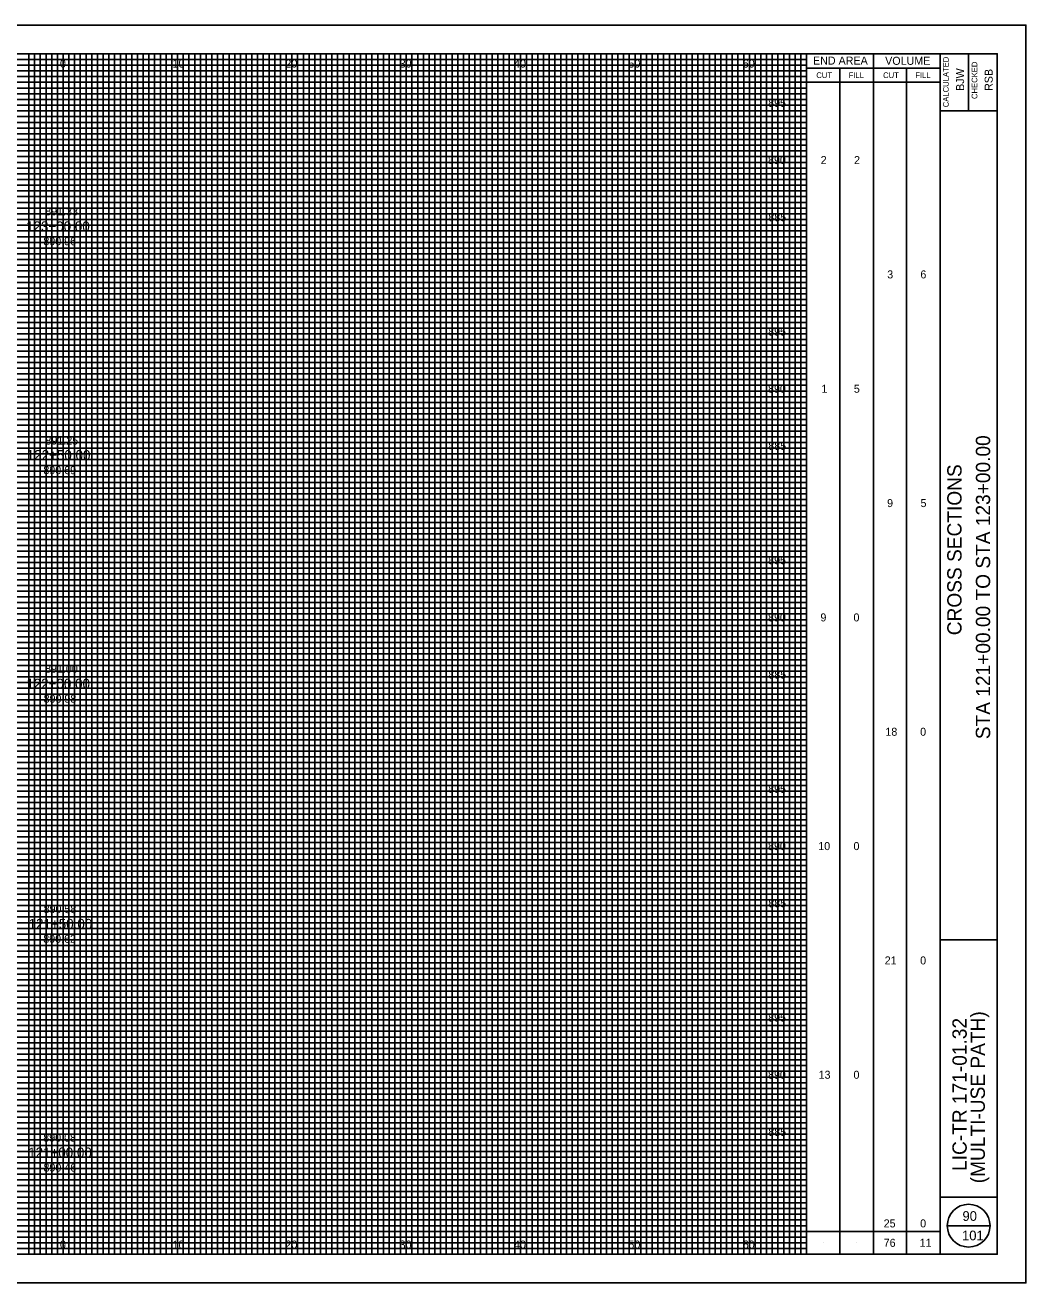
# Model space of a CAD drawing. Extents: x -10 to 160, y -2 to 3672.
# Drawn here: x 72.5 to 160, y 2412.5 to 2522.5 of the extents above; entities that cross this region are included whole.
import ezdxf

# ---------------------------------------------------------------- set-up
doc = ezdxf.new("R2010")
doc.units = 0
for name, color, linetype in [('SH_Border', 7, 'Continuous'), ('SH_Cut_Line', 7, 'Continuous'), ('SH_Data', 7, 'Continuous'), ('SH_Major_Grid_Line', 7, 'Continuous'), ('SH_Minor_Grid_Line', 7, 'Continuous'), ('SH_Text', 7, 'Continuous'), ('TX_P_10', 7, 'Continuous'), ('TX_X_10', 7, 'Continuous')]:
    doc.layers.add(name, color=color, linetype=linetype)

msp = doc.modelspace()

# ---------------------------------------------------------------- linework, layer by layer
at = {"layer": 'SH_Border'}
for p, q in [((152.5, 2415), (152.5, 2520)), ((155, 2520), (155, 2515)), ((152.5, 2515), (157.5, 2515)), ((152.5, 2442.5), (157.5, 2442.5)), ((152.5, 2420), (157.5, 2420))]:
    msp.add_line(p, q, dxfattribs=at)
msp.add_lwpolyline([(0, 2520), (157.5, 2520), (157.5, 2415), (0, 2415)], close=True, dxfattribs=at)
at = {"layer": 'SH_Cut_Line'}
msp.add_lwpolyline([(-10, 2412.5), (160, 2412.5), (160, 2522.5), (-10, 2522.5)], close=True, dxfattribs=at)
at = {"layer": 'SH_Data'}
for p, q in [((140.83, 2415), (140.83, 2520)), ((146.67, 2415), (146.67, 2520)), ((140.83, 2518.75), (152.5, 2518.75)), ((143.75, 2415), (143.75, 2518.75)), ((149.58, 2415), (149.58, 2518.75)), ((140.83, 2517.5), (152.5, 2517.5)), ((140.83, 2417), (152.5, 2417)), ((153.12, 2417.5), (156.88, 2417.5)), ((142.29, 2416), (142.29, 2416)), ((145.21, 2416), (145.21, 2416)), ((148.12, 2416), (148.12, 2416)), ((151.04, 2416), (151.04, 2416))]:
    msp.add_line(p, q, dxfattribs=at)
msp.add_circle((155, 2417.5), 1.87, dxfattribs=at)
at = {"layer": 'SH_Major_Grid_Line'}
for p, q in [((75.83, 2415), (75.83, 2520)), ((80.83, 2415), (80.83, 2520)), ((85.83, 2415), (85.83, 2520)), ((90.83, 2415), (90.83, 2520)), ((95.83, 2415), (95.83, 2520)), ((100.83, 2415), (100.83, 2520)), ((105.83, 2415), (105.83, 2520)), ((110.83, 2415), (110.83, 2520)), ((115.83, 2415), (115.83, 2520)), ((120.83, 2415), (120.83, 2520)), ((125.83, 2415), (125.83, 2520)), ((130.83, 2415), (130.83, 2520)), ((135.83, 2415), (135.83, 2520)), ((5.83, 2515), (140.83, 2515)), ((5.83, 2510), (140.83, 2510)), ((5.83, 2505), (140.83, 2505)), ((5.83, 2500), (140.83, 2500)), ((5.83, 2495), (140.83, 2495)), ((5.83, 2490), (140.83, 2490)), ((5.83, 2485), (140.83, 2485)), ((5.83, 2480), (140.83, 2480)), ((5.83, 2475), (140.83, 2475)), ((5.83, 2470), (140.83, 2470)), ((5.83, 2465), (140.83, 2465)), ((5.83, 2460), (140.83, 2460)), ((5.83, 2455), (140.83, 2455)), ((5.83, 2450), (140.83, 2450)), ((5.83, 2445), (140.83, 2445)), ((5.83, 2440), (140.83, 2440)), ((5.83, 2435), (140.83, 2435)), ((5.83, 2430), (140.83, 2430)), ((5.83, 2425), (140.83, 2425)), ((5.83, 2420), (140.83, 2420))]:
    msp.add_line(p, q, dxfattribs=at)
at = {"layer": 'SH_Minor_Grid_Line'}
for p, q in [((5.83, 2519.5), (140.83, 2519.5)), ((5.83, 2519), (140.83, 2519)), ((72.83, 2415), (72.83, 2520)), ((73.33, 2415), (73.33, 2520)), ((73.83, 2415), (73.83, 2520)), ((74.33, 2415), (74.33, 2520)), ((74.83, 2415), (74.83, 2520)), ((75.33, 2415), (75.33, 2520)), ((76.33, 2415), (76.33, 2520)), ((76.83, 2415), (76.83, 2520)), ((77.33, 2415), (77.33, 2520)), ((77.83, 2415), (77.83, 2520)), ((78.33, 2415), (78.33, 2520)), ((78.83, 2415), (78.83, 2520)), ((79.33, 2415), (79.33, 2520)), ((79.83, 2415), (79.83, 2520)), ((80.33, 2415), (80.33, 2520)), ((81.33, 2415), (81.33, 2520)), ((81.83, 2415), (81.83, 2520)), ((82.33, 2415), (82.33, 2520)), ((82.83, 2415), (82.83, 2520)), ((83.33, 2415), (83.33, 2520)), ((83.83, 2415), (83.83, 2520)), ((84.33, 2415), (84.33, 2520)), ((84.83, 2415), (84.83, 2520)), ((85.33, 2415), (85.33, 2520)), ((86.33, 2415), (86.33, 2520)), ((86.83, 2415), (86.83, 2520)), ((87.33, 2415), (87.33, 2520)), ((87.83, 2415), (87.83, 2520)), ((88.33, 2415), (88.33, 2520)), ((88.83, 2415), (88.83, 2520)), ((89.33, 2415), (89.33, 2520)), ((89.83, 2415), (89.83, 2520)), ((90.33, 2415), (90.33, 2520)), ((91.33, 2415), (91.33, 2520)), ((91.83, 2415), (91.83, 2520)), ((92.33, 2415), (92.33, 2520)), ((92.83, 2415), (92.83, 2520)), ((93.33, 2415), (93.33, 2520)), ((93.83, 2415), (93.83, 2520)), ((94.33, 2415), (94.33, 2520)), ((94.83, 2415), (94.83, 2520)), ((95.33, 2415), (95.33, 2520)), ((96.33, 2415), (96.33, 2520)), ((96.83, 2415), (96.83, 2520)), ((97.33, 2415), (97.33, 2520)), ((97.83, 2415), (97.83, 2520)), ((98.33, 2415), (98.33, 2520)), ((98.83, 2415), (98.83, 2520)), ((99.33, 2415), (99.33, 2520)), ((99.83, 2415), (99.83, 2520)), ((100.33, 2415), (100.33, 2520)), ((101.33, 2415), (101.33, 2520)), ((101.83, 2415), (101.83, 2520)), ((102.33, 2415), (102.33, 2520)), ((102.83, 2415), (102.83, 2520)), ((103.33, 2415), (103.33, 2520)), ((103.83, 2415), (103.83, 2520)), ((104.33, 2415), (104.33, 2520)), ((104.83, 2415), (104.83, 2520)), ((105.33, 2415), (105.33, 2520)), ((106.33, 2415), (106.33, 2520)), ((106.83, 2415), (106.83, 2520)), ((107.33, 2415), (107.33, 2520)), ((107.83, 2415), (107.83, 2520)), ((108.33, 2415), (108.33, 2520)), ((108.83, 2415), (108.83, 2520)), ((109.33, 2415), (109.33, 2520)), ((109.83, 2415), (109.83, 2520)), ((110.33, 2415), (110.33, 2520)), ((111.33, 2415), (111.33, 2520)), ((111.83, 2415), (111.83, 2520)), ((112.33, 2415), (112.33, 2520)), ((112.83, 2415), (112.83, 2520)), ((113.33, 2415), (113.33, 2520)), ((113.83, 2415), (113.83, 2520)), ((114.33, 2415), (114.33, 2520)), ((114.83, 2415), (114.83, 2520)), ((115.33, 2415), (115.33, 2520)), ((116.33, 2415), (116.33, 2520)), ((116.83, 2415), (116.83, 2520)), ((117.33, 2415), (117.33, 2520)), ((117.83, 2415), (117.83, 2520)), ((118.33, 2415), (118.33, 2520)), ((118.83, 2415), (118.83, 2520)), ((119.33, 2415), (119.33, 2520)), ((119.83, 2415), (119.83, 2520)), ((120.33, 2415), (120.33, 2520)), ((121.33, 2415), (121.33, 2520)), ((121.83, 2415), (121.83, 2520)), ((122.33, 2415), (122.33, 2520)), ((122.83, 2415), (122.83, 2520)), ((123.33, 2415), (123.33, 2520)), ((123.83, 2415), (123.83, 2520)), ((124.33, 2415), (124.33, 2520)), ((124.83, 2415), (124.83, 2520)), ((125.33, 2415), (125.33, 2520)), ((126.33, 2415), (126.33, 2520)), ((126.83, 2415), (126.83, 2520)), ((127.33, 2415), (127.33, 2520)), ((127.83, 2415), (127.83, 2520)), ((128.33, 2415), (128.33, 2520)), ((128.83, 2415), (128.83, 2520)), ((129.33, 2415), (129.33, 2520)), ((129.83, 2415), (129.83, 2520)), ((130.33, 2415), (130.33, 2520)), ((131.33, 2415), (131.33, 2520)), ((131.83, 2415), (131.83, 2520)), ((132.33, 2415), (132.33, 2520)), ((132.83, 2415), (132.83, 2520)), ((133.33, 2415), (133.33, 2520)), ((133.83, 2415), (133.83, 2520)), ((134.33, 2415), (134.33, 2520)), ((134.83, 2415), (134.83, 2520)), ((135.33, 2415), (135.33, 2520)), ((136.33, 2415), (136.33, 2520)), ((136.83, 2415), (136.83, 2520)), ((137.33, 2415), (137.33, 2520)), ((137.83, 2415), (137.83, 2520)), ((138.33, 2415), (138.33, 2520)), ((138.83, 2415), (138.83, 2520)), ((139.33, 2415), (139.33, 2520)), ((139.83, 2415), (139.83, 2520)), ((140.33, 2415), (140.33, 2520)), ((5.83, 2518.5), (140.83, 2518.5)), ((5.83, 2518), (140.83, 2518)), ((5.83, 2517.5), (140.83, 2517.5)), ((5.83, 2517), (140.83, 2517)), ((5.83, 2516.5), (140.83, 2516.5)), ((5.83, 2516), (140.83, 2516)), ((5.83, 2515.5), (140.83, 2515.5)), ((5.83, 2514.5), (140.83, 2514.5)), ((5.83, 2514), (140.83, 2514)), ((5.83, 2513.5), (140.83, 2513.5)), ((5.83, 2513), (140.83, 2513)), ((5.83, 2512.5), (140.83, 2512.5)), ((5.83, 2512), (140.83, 2512)), ((5.83, 2511.5), (140.83, 2511.5)), ((5.83, 2511), (140.83, 2511)), ((5.83, 2510.5), (140.83, 2510.5)), ((5.83, 2509.5), (140.83, 2509.5)), ((5.83, 2509), (140.83, 2509)), ((5.83, 2508.5), (140.83, 2508.5)), ((5.83, 2508), (140.83, 2508)), ((5.83, 2507.5), (140.83, 2507.5)), ((5.83, 2507), (140.83, 2507)), ((5.83, 2506.5), (140.83, 2506.5)), ((5.83, 2506), (140.83, 2506)), ((5.83, 2505.5), (140.83, 2505.5)), ((5.83, 2504.5), (140.83, 2504.5)), ((5.83, 2504), (140.83, 2504)), ((5.83, 2503.5), (140.83, 2503.5)), ((5.83, 2503), (140.83, 2503)), ((5.83, 2502.5), (140.83, 2502.5)), ((5.83, 2502), (140.83, 2502)), ((5.83, 2501.5), (140.83, 2501.5)), ((5.83, 2501), (140.83, 2501)), ((5.83, 2500.5), (140.83, 2500.5)), ((5.83, 2499.5), (140.83, 2499.5)), ((5.83, 2499), (140.83, 2499)), ((5.83, 2498.5), (140.83, 2498.5)), ((5.83, 2498), (140.83, 2498)), ((5.83, 2497.5), (140.83, 2497.5)), ((5.83, 2497), (140.83, 2497)), ((5.83, 2496.5), (140.83, 2496.5)), ((5.83, 2496), (140.83, 2496)), ((5.83, 2495.5), (140.83, 2495.5)), ((5.83, 2494.5), (140.83, 2494.5)), ((5.83, 2494), (140.83, 2494)), ((5.83, 2493.5), (140.83, 2493.5)), ((5.83, 2493), (140.83, 2493)), ((5.83, 2492.5), (140.83, 2492.5)), ((5.83, 2492), (140.83, 2492)), ((5.83, 2491.5), (140.83, 2491.5)), ((5.83, 2491), (140.83, 2491)), ((5.83, 2490.5), (140.83, 2490.5)), ((5.83, 2489.5), (140.83, 2489.5)), ((5.83, 2489), (140.83, 2489)), ((5.83, 2488.5), (140.83, 2488.5)), ((5.83, 2488), (140.83, 2488)), ((5.83, 2487.5), (140.83, 2487.5)), ((5.83, 2487), (140.83, 2487)), ((5.83, 2486.5), (140.83, 2486.5)), ((5.83, 2486), (140.83, 2486)), ((5.83, 2485.5), (140.83, 2485.5)), ((5.83, 2484.5), (140.83, 2484.5)), ((5.83, 2484), (140.83, 2484)), ((5.83, 2483.5), (140.83, 2483.5)), ((5.83, 2483), (140.83, 2483)), ((5.83, 2482.5), (140.83, 2482.5)), ((5.83, 2482), (140.83, 2482)), ((5.83, 2481.5), (140.83, 2481.5)), ((5.83, 2481), (140.83, 2481)), ((5.83, 2480.5), (140.83, 2480.5)), ((5.83, 2479.5), (140.83, 2479.5)), ((5.83, 2479), (140.83, 2479)), ((5.83, 2478.5), (140.83, 2478.5)), ((5.83, 2478), (140.83, 2478)), ((5.83, 2477.5), (140.83, 2477.5)), ((5.83, 2477), (140.83, 2477)), ((5.83, 2476.5), (140.83, 2476.5)), ((5.83, 2476), (140.83, 2476)), ((5.83, 2475.5), (140.83, 2475.5)), ((5.83, 2474.5), (140.83, 2474.5)), ((5.83, 2474), (140.83, 2474)), ((5.83, 2473.5), (140.83, 2473.5)), ((5.83, 2473), (140.83, 2473)), ((5.83, 2472.5), (140.83, 2472.5)), ((5.83, 2472), (140.83, 2472)), ((5.83, 2471.5), (140.83, 2471.5)), ((5.83, 2471), (140.83, 2471)), ((5.83, 2470.5), (140.83, 2470.5)), ((5.83, 2469.5), (140.83, 2469.5)), ((5.83, 2469), (140.83, 2469)), ((5.83, 2468.5), (140.83, 2468.5)), ((5.83, 2468), (140.83, 2468)), ((5.83, 2467.5), (140.83, 2467.5)), ((5.83, 2467), (140.83, 2467)), ((5.83, 2466.5), (140.83, 2466.5)), ((5.83, 2466), (140.83, 2466)), ((5.83, 2465.5), (140.83, 2465.5)), ((5.83, 2464.5), (140.83, 2464.5)), ((5.83, 2464), (140.83, 2464)), ((5.83, 2463.5), (140.83, 2463.5)), ((5.83, 2463), (140.83, 2463)), ((5.83, 2462.5), (140.83, 2462.5)), ((5.83, 2462), (140.83, 2462)), ((5.83, 2461.5), (140.83, 2461.5)), ((5.83, 2461), (140.83, 2461)), ((5.83, 2460.5), (140.83, 2460.5)), ((5.83, 2459.5), (140.83, 2459.5)), ((5.83, 2459), (140.83, 2459)), ((5.83, 2458.5), (140.83, 2458.5)), ((5.83, 2458), (140.83, 2458)), ((5.83, 2457.5), (140.83, 2457.5)), ((5.83, 2457), (140.83, 2457)), ((5.83, 2456.5), (140.83, 2456.5)), ((5.83, 2456), (140.83, 2456)), ((5.83, 2455.5), (140.83, 2455.5)), ((5.83, 2454.5), (140.83, 2454.5)), ((5.83, 2454), (140.83, 2454)), ((5.83, 2453.5), (140.83, 2453.5)), ((5.83, 2453), (140.83, 2453)), ((5.83, 2452.5), (140.83, 2452.5)), ((5.83, 2452), (140.83, 2452)), ((5.83, 2451.5), (140.83, 2451.5)), ((5.83, 2451), (140.83, 2451)), ((5.83, 2450.5), (140.83, 2450.5)), ((5.83, 2449.5), (140.83, 2449.5)), ((5.83, 2449), (140.83, 2449)), ((5.83, 2448.5), (140.83, 2448.5)), ((5.83, 2448), (140.83, 2448)), ((5.83, 2447.5), (140.83, 2447.5)), ((5.83, 2447), (140.83, 2447)), ((5.83, 2446.5), (140.83, 2446.5)), ((5.83, 2446), (140.83, 2446)), ((5.83, 2445.5), (140.83, 2445.5)), ((5.83, 2444.5), (140.83, 2444.5)), ((5.83, 2444), (140.83, 2444)), ((5.83, 2443.5), (140.83, 2443.5)), ((5.83, 2443), (140.83, 2443)), ((5.83, 2442.5), (140.83, 2442.5)), ((5.83, 2442), (140.83, 2442)), ((5.83, 2441.5), (140.83, 2441.5)), ((5.83, 2441), (140.83, 2441)), ((5.83, 2440.5), (140.83, 2440.5)), ((5.83, 2439.5), (140.83, 2439.5)), ((5.83, 2439), (140.83, 2439)), ((5.83, 2438.5), (140.83, 2438.5)), ((5.83, 2438), (140.83, 2438)), ((5.83, 2437.5), (140.83, 2437.5)), ((5.83, 2437), (140.83, 2437)), ((5.83, 2436.5), (140.83, 2436.5)), ((5.83, 2436), (140.83, 2436)), ((5.83, 2435.5), (140.83, 2435.5)), ((5.83, 2434.5), (140.83, 2434.5)), ((5.83, 2434), (140.83, 2434)), ((5.83, 2433.5), (140.83, 2433.5)), ((5.83, 2433), (140.83, 2433)), ((5.83, 2432.5), (140.83, 2432.5)), ((5.83, 2432), (140.83, 2432)), ((5.83, 2431.5), (140.83, 2431.5)), ((5.83, 2431), (140.83, 2431)), ((5.83, 2430.5), (140.83, 2430.5)), ((5.83, 2429.5), (140.83, 2429.5)), ((5.83, 2429), (140.83, 2429)), ((5.83, 2428.5), (140.83, 2428.5)), ((5.83, 2428), (140.83, 2428)), ((5.83, 2427.5), (140.83, 2427.5)), ((5.83, 2427), (140.83, 2427)), ((5.83, 2426.5), (140.83, 2426.5)), ((5.83, 2426), (140.83, 2426)), ((5.83, 2425.5), (140.83, 2425.5)), ((5.83, 2424.5), (140.83, 2424.5)), ((5.83, 2424), (140.83, 2424)), ((5.83, 2423.5), (140.83, 2423.5)), ((5.83, 2423), (140.83, 2423)), ((5.83, 2422.5), (140.83, 2422.5)), ((5.83, 2422), (140.83, 2422)), ((5.83, 2421.5), (140.83, 2421.5)), ((5.83, 2421), (140.83, 2421)), ((5.83, 2420.5), (140.83, 2420.5)), ((5.83, 2419.5), (140.83, 2419.5)), ((5.83, 2419), (140.83, 2419)), ((5.83, 2418.5), (140.83, 2418.5)), ((5.83, 2418), (140.83, 2418)), ((5.83, 2417.5), (140.83, 2417.5)), ((5.83, 2417), (140.83, 2417)), ((5.83, 2416.5), (140.83, 2416.5)), ((5.83, 2416), (140.83, 2416)), ((5.83, 2415.5), (140.83, 2415.5))]:
    msp.add_line(p, q, dxfattribs=at)

# ---------------------------------------------------------------- texts
at = {"layer": 'SH_Data'}
for s, height, p in [('END AREA', 0.7, (141.39, 2519.05)), ('VOLUME', 0.7, (147.7, 2519.03)), ('CUT', 0.5, (141.68, 2517.87)), ('FILL', 0.5, (144.5, 2517.87)), ('CUT', 0.5, (147.52, 2517.87)), ('FILL', 0.5, (150.34, 2517.87)), ('90', 0.85, (154.46, 2417.92)), ('101', 0.85, (154.42, 2416.22))]:
    msp.add_text(s, height=height, dxfattribs=at).set_placement(p)
for s, height, p in [('CALCULATED', 0.5, (153.26, 2515.32)), ('CHECKED', 0.5, (155.76, 2516.04)), ('BJW', 0.7, (154.6, 2516.75)), ('RSB', 0.7, (157.1, 2516.75)), ('STA 121+00.00 TO STA 123+00.00', 1.25, (156.88, 2460.05)), ('CROSS SECTIONS', 1.25, (154.38, 2469.14)), ('LIC-TR 171-01.32', 1.25, (154.83, 2422.29)), ('(MULTI-USE PATH)', 1.25, (156.42, 2421.21))]:
    msp.add_text(s, height=height, rotation=90, dxfattribs=at).set_placement(p)
at = {"layer": 'SH_Text'}
for s, height, p in [('0', 0.7, (75.55, 2518.79)), ('10', 0.7, (85.39, 2518.79)), ('20', 0.7, (95.26, 2518.79)), ('30', 0.7, (105.25, 2518.79)), ('40', 0.7, (115.25, 2518.79)), ('50', 0.7, (125.25, 2518.79)), ('60', 0.7, (135.25, 2518.79)), ('895', 0.7, (137.47, 2515.35)), ('890', 0.7, (137.46, 2510.35)), ('2', 0.7, (142.06, 2510.35)), ('2', 0.7, (144.98, 2510.35)), ('885', 0.7, (137.48, 2505.35)), ('123+00.00', 0.875, (72.59, 2504.46)), ('3', 0.7, (147.88, 2500.35)), ('6', 0.7, (150.78, 2500.35)), ('895', 0.7, (137.47, 2495.35)), ('890', 0.7, (137.46, 2490.35)), ('1', 0.7, (142.13, 2490.35)), ('5', 0.7, (144.96, 2490.35)), ('885', 0.7, (137.48, 2485.35)), ('122+50.00', 0.875, (72.65, 2484.46)), ('9', 0.7, (147.87, 2480.35)), ('5', 0.7, (150.79, 2480.35)), ('895', 0.7, (137.47, 2475.35)), ('890', 0.7, (137.46, 2470.35)), ('9', 0.7, (142.04, 2470.35)), ('0', 0.7, (144.93, 2470.35)), ('122+00.00', 0.875, (72.61, 2464.46)), ('885', 0.7, (137.48, 2465.35)), ('18', 0.7, (147.72, 2460.35)), ('0', 0.7, (150.76, 2460.35)), ('895', 0.7, (137.47, 2455.35)), ('890', 0.7, (137.46, 2450.35)), ('10', 0.7, (141.85, 2450.35)), ('0', 0.7, (144.93, 2450.35)), ('885', 0.7, (137.48, 2445.35)), ('121+50.00', 0.875, (72.81, 2443.46)), ('21', 0.7, (147.66, 2440.35)), ('0', 0.7, (150.76, 2440.35)), ('895', 0.7, (137.47, 2435.35)), ('890', 0.7, (137.46, 2430.35)), ('13', 0.7, (141.88, 2430.35)), ('0', 0.7, (144.93, 2430.35)), ('885', 0.7, (137.48, 2425.35)), ('121+00.00', 0.875, (72.77, 2423.46)), ('25', 0.7, (147.57, 2417.35)), ('0', 0.7, (150.76, 2417.35)), ('0', 0.7, (75.55, 2415.5)), ('10', 0.7, (85.39, 2415.5)), ('20', 0.7, (95.26, 2415.5)), ('30', 0.7, (105.25, 2415.5)), ('40', 0.7, (115.25, 2415.5)), ('50', 0.7, (125.25, 2415.5)), ('60', 0.7, (135.25, 2415.5)), ('76', 0.7, (147.57, 2415.65)), ('11', 0.7, (150.71, 2415.65))]:
    msp.add_text(s, height=height, dxfattribs=at).set_placement(p)
at = {"layer": 'TX_P_10'}
for s, p in [('891.33', (74.26, 2505.87)), ('891.25', (74.28, 2485.82)), ('891.00', (74.25, 2465.87)), ('890.58', (74.12, 2444.84)), ('890.08', (74.09, 2424.85))]:
    msp.add_text(s, height=0.7, dxfattribs=at).set_placement(p)
at = {"layer": 'TX_X_10'}
for s, p in [('890.96', (74.1, 2503.25)), ('890.69', (74.1, 2483.23)), ('890.98', (74.12, 2463.24)), ('890.62', (74.09, 2442.24)), ('890.46', (74.11, 2422.23))]:
    msp.add_text(s, height=0.7, dxfattribs=at).set_placement(p)

doc.saveas('drawing.dxf')
